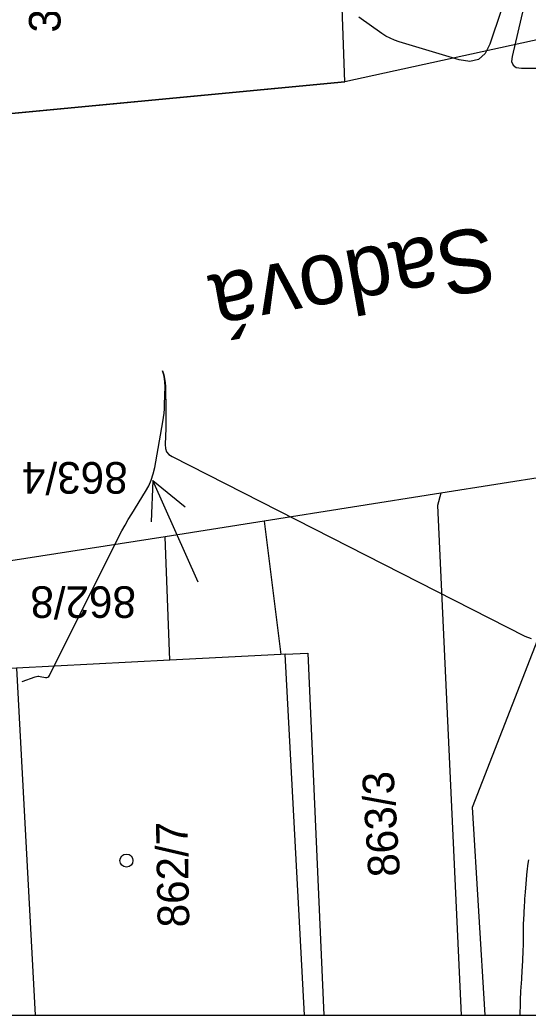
# Model space of a CAD drawing. Extents: x -534410 to -534262, y -1190162 to -1189584.
# Drawn here: x -534360.56 to -534346.89, y -1190161.97 to -1190135.2 of the extents above; entities that cross this region are included whole.
import ezdxf

# ---------------------------------------------------------------- set-up
doc = ezdxf.new("R2010")
doc.units = 0
for name, color, linetype in [('30', 7, 'Continuous'), ('31', 7, 'Continuous'), ('_rámeček', 7, 'Continuous'), ('_rámeček_mřížka', 7, 'Continuous'), ('Hranice parcel', 7, 'Continuous'), ('Parcelní čísla', 7, 'Continuous'), ('Polygon budovy', 7, 'Continuous'), ('Pop  PČ popisy', 7, 'Continuous'), ('Značky budov', 7, 'Continuous')]:
    doc.layers.add(name, color=color, linetype=linetype)

msp = doc.modelspace()

# ---------------------------------------------------------------- linework, layer by layer
at = {"layer": '30'}
msp.add_lwpolyline([(-534360.503, -1190152.994), (-534360.156, -1190152.869), (-534360.121, -1190152.859), (-534360.086, -1190152.854), (-534360.051, -1190152.854), (-534360.015, -1190152.859), (-534359.872, -1190152.887), (-534359.838, -1190152.889), (-534359.81, -1190152.881), (-534359.786, -1190152.864), (-534359.767, -1190152.836), (-534357.9, -1190149.097), (-534357.82, -1190148.941), (-534357.736, -1190148.787), (-534357.648, -1190148.635), (-534357.557, -1190148.484), (-534357.185, -1190147.887), (-534357.099, -1190147.735), (-534357.03, -1190147.577), (-534356.975, -1190147.413), (-534356.937, -1190147.243), (-534356.717, -1190146.007), (-534356.698, -1190145.892), (-534356.685, -1190145.776), (-534356.675, -1190145.66), (-534356.67, -1190145.544), (-534356.659, -1190145.058), (-534356.661, -1190144.952), (-534356.672, -1190144.848), (-534356.694, -1190144.745), (-534356.725, -1190144.643), (-534356.693, -1190144.745), (-534356.67, -1190144.848), (-534356.655, -1190144.952), (-534356.649, -1190145.058), (-534356.635, -1190145.735), (-534356.634, -1190145.846), (-534356.634, -1190145.957), (-534356.636, -1190146.068), (-534356.64, -1190146.179), (-534356.659, -1190146.623), (-534356.651, -1190146.726), (-534356.617, -1190146.814), (-534356.556, -1190146.887), (-534356.47, -1190146.945), (-534346.982, -1190151.777), (-534346.812, -1190151.837)], dxfattribs=at)
at = {"layer": '31'}
for points in [[(-534345.774, -1190129.479), (-534347.917, -1190135.848), (-534348.046, -1190136.106), (-534348.228, -1190136.263), (-534348.461, -1190136.32), (-534348.746, -1190136.276), (-534350.357, -1190135.789), (-534350.482, -1190135.746), (-534350.602, -1190135.694), (-534350.718, -1190135.632), (-534350.829, -1190135.561), (-534351.449, -1190135.128)], [(-534345.799, -1190129.628), (-534347.323, -1190136.18), (-534347.334, -1190136.319), (-534347.296, -1190136.418), (-534347.208, -1190136.478), (-534347.07, -1190136.498), (-534346.176, -1190136.498)], [(-534346.884, -1190157.791), (-534346.906, -1190157.942), (-534346.911, -1190157.98), (-534346.916, -1190158.018), (-534346.92, -1190158.056), (-534346.923, -1190158.094), (-534346.972, -1190158.666), (-534346.98, -1190158.755), (-534346.986, -1190158.845), (-534346.992, -1190158.934), (-534346.997, -1190159.024), (-534347.018, -1190159.421), (-534347.021, -1190159.491), (-534347.024, -1190159.562), (-534347.025, -1190159.633), (-534347.026, -1190159.703), (-534347.026, -1190159.986), (-534347.026, -1190160.056), (-534347.027, -1190160.127), (-534347.029, -1190160.198), (-534347.032, -1190160.268), (-534347.052, -1190160.684), (-534347.056, -1190160.764), (-534347.061, -1190160.844), (-534347.066, -1190160.924), (-534347.071, -1190161.004), (-534347.092, -1190161.324), (-534347.097, -1190161.404), (-534347.101, -1190161.484), (-534347.104, -1190161.564), (-534347.105, -1190161.645), (-534347.109, -1190161.97)]]:
    msp.add_lwpolyline(points, dxfattribs=at)
at = {"layer": '_rámeček'}
msp.add_lwpolyline([(-534410.126, -1190161.97), (-534261.626, -1190161.97), (-534261.626, -1189584.47)], dxfattribs=at)
at = {"layer": '_rámeček_mřížka'}
msp.add_lwpolyline([(-534410.126, -1190161.97), (-534261.626, -1190161.97), (-534261.626, -1189584.47)], dxfattribs=at)
at = {"layer": 'Hranice parcel'}
for p, q in [((-534344.25, -1190135.21), (-534351.82, -1190136.86)), ((-534351.82, -1190136.86), (-534367.59, -1190138.36)), ((-534344.83, -1190147.24), (-534349.24, -1190147.93)), ((-534349.24, -1190147.93), (-534353.99, -1190148.68)), ((-534353.99, -1190148.68), (-534356.66, -1190149.1)), ((-534353.99, -1190148.68), (-534353.54, -1190152.27)), ((-534356.53, -1190152.42), (-534356.66, -1190149.1)), ((-534353.54, -1190152.27), (-534356.53, -1190152.42)), ((-534353.43, -1190152.26), (-534353.54, -1190152.27))]:
    msp.add_line(p, q, dxfattribs=at)
for points in [[(-534351.82, -1190136.86), (-534352.07, -1190129.87), (-534352.17, -1190126.76), (-534357.34, -1190124.5), (-534362.92, -1190124.6), (-534362.95, -1190121.17), (-534367.57, -1190121.12)], [(-534348.046, -1190161.97), (-534348.39, -1190156.38), (-534344.83, -1190147.24)], [(-534349.24, -1190147.93), (-534349.33, -1190148.26), (-534348.688, -1190161.97)], [(-534356.66, -1190149.1), (-534360.81, -1190149.75), (-534361.7, -1190149.89)], [(-534353.43, -1190152.26), (-534352.82, -1190152.23), (-534352.39, -1190161.97)], [(-534352.903, -1190161.97), (-534353.43, -1190152.26)], [(-534356.53, -1190152.42), (-534360.66, -1190152.64), (-534361.51, -1190152.68)]]:
    msp.add_lwpolyline(points, dxfattribs=at)
at = {"layer": 'Polygon budovy'}
msp.add_line((-534360.154, -1190161.97), (-534352.903, -1190161.97), dxfattribs=at)
msp.add_lwpolyline([(-534351.82, -1190136.86), (-534352.07, -1190129.87), (-534360.72, -1190130.62), (-534360.69, -1190125.75), (-534363.02, -1190125.69), (-534362.92, -1190124.6), (-534362.95, -1190121.17), (-534367.57, -1190121.12), (-534367.61, -1190129.31), (-534367.59, -1190138.36)], close=True, dxfattribs=at)
msp.add_lwpolyline([(-534352.903, -1190161.97), (-534353.43, -1190152.26), (-534353.54, -1190152.27), (-534356.53, -1190152.42), (-534360.66, -1190152.64), (-534360.154, -1190161.97)], dxfattribs=at)
at = {"layer": 'Pop  PČ popisy'}
for p, q in [((-534356.987, -1190147.586), (-534357.037, -1190148.705)), ((-534355.766, -1190150.328), (-534356.987, -1190147.586)), ((-534356.987, -1190147.586), (-534356.122, -1190148.298))]:
    msp.add_line(p, q, dxfattribs=at)
at = {"layer": 'Značky budov'}
msp.add_circle((-534357.697, -1190157.813), 0.175, dxfattribs=at)

# ---------------------------------------------------------------- texts
at = {"layer": 'Parcelní čísla'}
for s, rotation, p in [('3079/1', 90, (-534359.471, -1190135.541)), ('863/4', 180, (-534357.665, -1190147.093)), ('862/8', 180, (-534357.44, -1190150.435)), ('863/3', 93.6145, (-534350.334, -1190158.227)), ('862/7', 91, (-534356.005, -1190159.605))]:
    msp.add_text(s, height=0.85, rotation=rotation, dxfattribs=at).set_placement(p)
at = {"layer": 'Pop  PČ popisy'}
msp.add_text('Sadová', height=1.7, rotation=190.1952, dxfattribs=at).set_placement((-534347.944, -1190140.72))

doc.saveas('drawing.dxf')
